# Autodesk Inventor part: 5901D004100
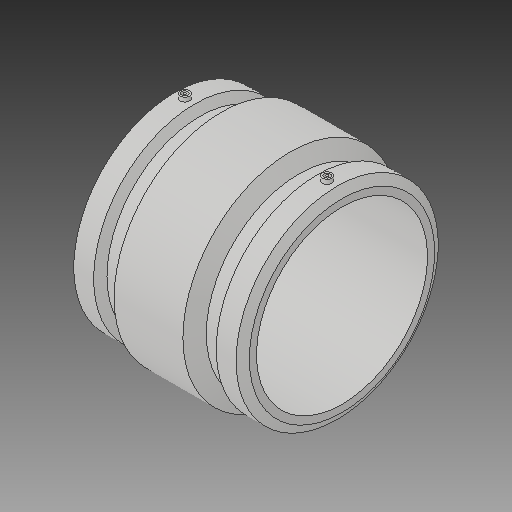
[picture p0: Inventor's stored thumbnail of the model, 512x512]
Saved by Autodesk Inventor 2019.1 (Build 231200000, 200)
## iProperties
Created: 2017-06
Part Number: 5901D004100
Material: Generic
Description: PLASSON COUPLER 10''DIPS
Document SubType Name: Modeling
Designer: KIM
Mass: 96874 g
Surface Area: 34549.7 cm^2
Volume: 96874 cm^3
Density: 1 g/cm^3
Appearance: Default
Author: KIM
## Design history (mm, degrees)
derived "5901D.ipt"
feature "Solid1::5901D.ipt"
tag "TaggingFeature1"
body "Solid1"
other parameters: "d13" = 274.32, "d15" = 134.874, "d16" = 134.874, "d17" = 272.7, "d22" = 335.788, "d23" = 342.9, "d24" = 295.49344, "d25" = 150 deg, "d26" = 109.728, "d27" = 120 deg, "d29" = 167.894, "d35" = 15, "d39" = 0, "d40" = 4, "d41" = 14, "d42" = 0, "d44" = 47.2059, "d45" = 272.7, "d47" = 0, "d48" = 161.17824, "d49" = 47.2059, "d50" = 60 deg, "d57" = 65.786, "d58" = 47.2059, "d62" = 272.7, "d65" = 282.448, "d67" = 5.27613, "d68" = 21.15863, "d69" = 21.80789, "d70" = 21.71015, "d71" = 20.5722, "d72" = 20.71531, "d73" = 561.2638, "d76" = 109.728, "d77" = 295.49344, "d_" = 272.7, "L_" = 274.32, "L_1" = 134.874, "D_" = 342.9, "A_" = 167.894, "A_1" = 25.4, "d60" = 187.96
